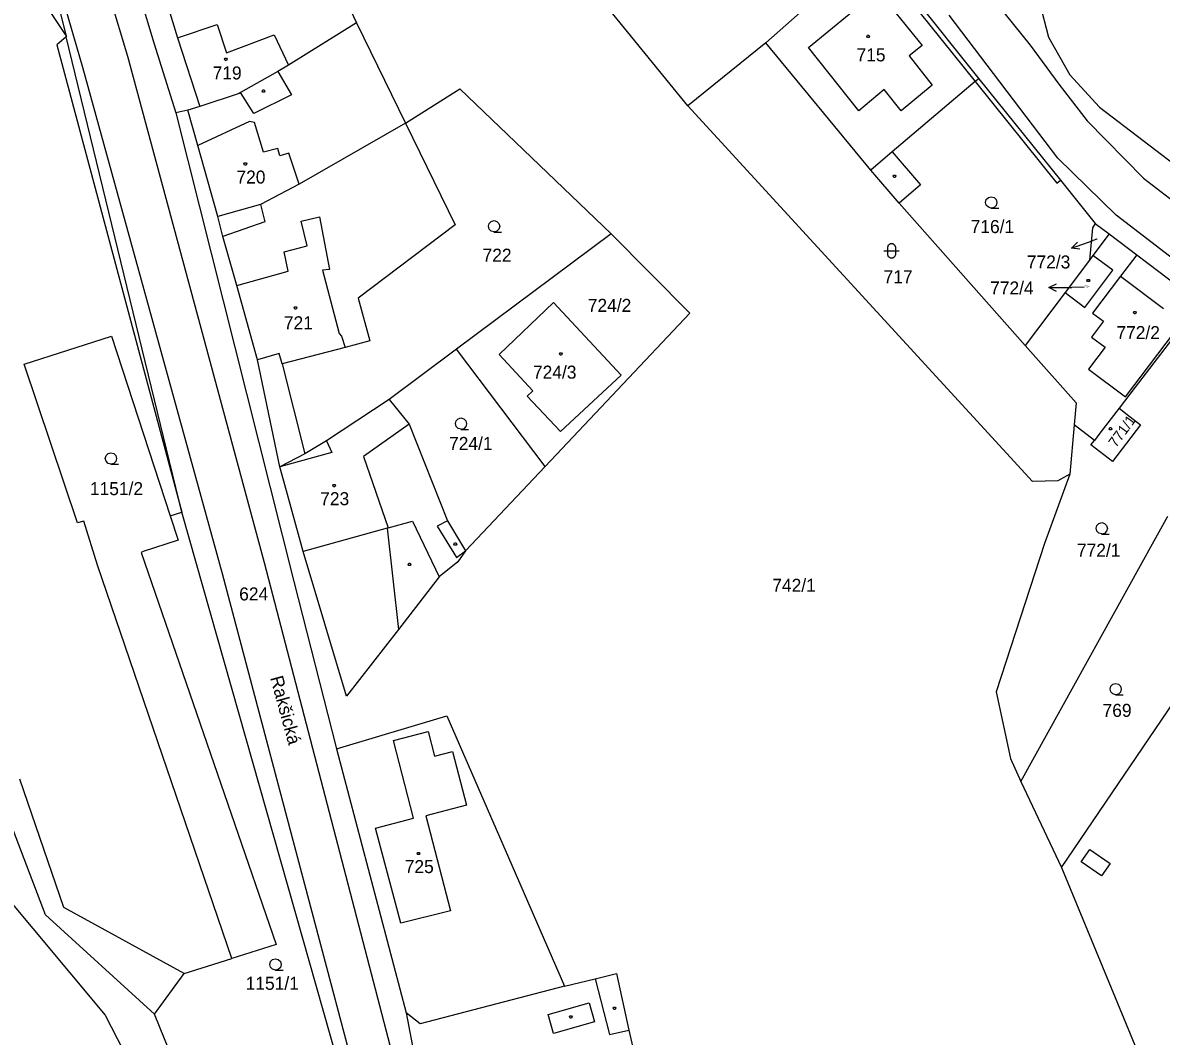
# Model space of a CAD drawing. Extents: x -621797 to -620972, y -1175539 to -1174697.
# Drawn here: x -621354.5 to -621205.7, y -1175263 to -1175130.5 of the extents above; entities that cross this region are included whole.
import ezdxf

# ---------------------------------------------------------------- set-up
doc = ezdxf.new("R2010")
doc.units = 0
for name, color, linetype in [('INZ mimo EON - nadz', 7, 'Continuous'), ('Rozvod plynu EON', 7, 'Continuous'), ('SDEL EON', 7, 'Continuous'), ('SDEL EON - popis', 7, 'Continuous'), ('Silnoproud EON', 7, 'Continuous'), ('Silnoproud EON - popis', 7, 'Continuous')]:
    doc.layers.add(name, color=color, linetype=linetype)

msp = doc.modelspace()

# ---------------------------------------------------------------- linework, layer by layer
at = {"layer": 'INZ mimo EON - nadz'}
for p, q in [((-621214.09, -1175158.81), (-621214.59, -1175158.99)), ((-621217.407, -1175160.022), (-621214.59, -1175158.99)), ((-621220.37, -1175165.164), (-621217.37, -1175165.13)), ((-621215.74, -1175165.11), (-621217.37, -1175165.13))]:
    msp.add_line(p, q, dxfattribs=at)
for points in [[(-621216.296, -1175160.148), (-621217.407, -1175160.022), (-621216.64, -1175159.209)], [(-621219.364, -1175165.652), (-621220.37, -1175165.164), (-621219.375, -1175164.652)]]:
    msp.add_lwpolyline(points, dxfattribs=at)
at = {"layer": 'Rozvod plynu EON'}
for points in [[(-621243.88, -1175132.18), (-621243.79, -1175132.33), (-621243.88, -1175132.48), (-621244.06, -1175132.48), (-621244.15, -1175132.33), (-621244.06, -1175132.18)], [(-621327.84, -1175135.17), (-621327.75, -1175135.32), (-621327.84, -1175135.47), (-621328.02, -1175135.47), (-621328.11, -1175135.32), (-621328.02, -1175135.17)], [(-621322.93, -1175139.33), (-621322.84, -1175139.48), (-621322.93, -1175139.63), (-621323.11, -1175139.63), (-621323.2, -1175139.48), (-621323.11, -1175139.33)], [(-621325.3, -1175148.84), (-621325.21, -1175148.99), (-621325.3, -1175149.14), (-621325.48, -1175149.14), (-621325.57, -1175148.99), (-621325.48, -1175148.84)], [(-621240.45, -1175150.45), (-621240.36, -1175150.6), (-621240.45, -1175150.75), (-621240.63, -1175150.75), (-621240.72, -1175150.6), (-621240.63, -1175150.45)], [(-621215.11, -1175164.08), (-621215.02, -1175164.23), (-621215.11, -1175164.38), (-621215.29, -1175164.38), (-621215.38, -1175164.23), (-621215.29, -1175164.08)], [(-621318.73, -1175167.67), (-621318.64, -1175167.82), (-621318.73, -1175167.97), (-621318.91, -1175167.97), (-621319, -1175167.82), (-621318.91, -1175167.67)], [(-621209.02, -1175168.28), (-621208.93, -1175168.43), (-621209.02, -1175168.58), (-621209.2, -1175168.58), (-621209.29, -1175168.43), (-621209.2, -1175168.28)], [(-621284.06, -1175173.67), (-621283.97, -1175173.82), (-621284.06, -1175173.97), (-621284.24, -1175173.97), (-621284.33, -1175173.82), (-621284.24, -1175173.67)], [(-621212.22, -1175183.45), (-621212.13, -1175183.6), (-621212.22, -1175183.75), (-621212.4, -1175183.75), (-621212.49, -1175183.6), (-621212.4, -1175183.45)], [(-621313.69, -1175190.88), (-621313.6, -1175191.03), (-621313.69, -1175191.18), (-621313.87, -1175191.18), (-621313.96, -1175191.03), (-621313.87, -1175190.88)], [(-621297.85, -1175198.53), (-621297.76, -1175198.68), (-621297.85, -1175198.83), (-621298.03, -1175198.83), (-621298.12, -1175198.68), (-621298.03, -1175198.53)], [(-621303.84, -1175201.19), (-621303.75, -1175201.34), (-621303.84, -1175201.49), (-621304.02, -1175201.49), (-621304.11, -1175201.34), (-621304.02, -1175201.19)], [(-621302.68, -1175238.98), (-621302.59, -1175239.13), (-621302.68, -1175239.28), (-621302.86, -1175239.28), (-621302.95, -1175239.13), (-621302.86, -1175238.98)], [(-621277.06, -1175259.21), (-621276.97, -1175259.36), (-621277.06, -1175259.51), (-621277.24, -1175259.51), (-621277.33, -1175259.36), (-621277.24, -1175259.21)], [(-621282.76, -1175260.34), (-621282.67, -1175260.49), (-621282.76, -1175260.64), (-621282.94, -1175260.64), (-621283.03, -1175260.49), (-621282.94, -1175260.34)]]:
    msp.add_lwpolyline(points, close=True, dxfattribs=at)
at = {"layer": 'SDEL EON'}
for points in [[(-621227.89, -1175154.76), (-621228.27, -1175154.66), (-621228.54, -1175154.39), (-621228.64, -1175154.02), (-621228.54, -1175153.65), (-621228.27, -1175153.38), (-621227.9, -1175153.28), (-621227.53, -1175153.38), (-621227.26, -1175153.65), (-621227.16, -1175154.03), (-621227.26, -1175154.41), (-621227.53, -1175154.68), (-621227.91, -1175154.78), (-621226.91, -1175154.78)], [(-621292.87, -1175157.88), (-621293.25, -1175157.78), (-621293.52, -1175157.51), (-621293.62, -1175157.14), (-621293.52, -1175156.77), (-621293.25, -1175156.5), (-621292.88, -1175156.4), (-621292.51, -1175156.5), (-621292.24, -1175156.77), (-621292.14, -1175157.15), (-621292.24, -1175157.53), (-621292.51, -1175157.8), (-621292.89, -1175157.9), (-621291.89, -1175157.9)], [(-621241.93, -1175160.36), (-621240.66, -1175160.36), (-621239.93, -1175160.36)], [(-621297.19, -1175183.68), (-621297.57, -1175183.58), (-621297.84, -1175183.31), (-621297.94, -1175182.94), (-621297.84, -1175182.57), (-621297.57, -1175182.3), (-621297.2, -1175182.2), (-621296.83, -1175182.3), (-621296.56, -1175182.57), (-621296.46, -1175182.95), (-621296.56, -1175183.33), (-621296.83, -1175183.6), (-621297.21, -1175183.7), (-621296.21, -1175183.7)], [(-621342.95, -1175188.23), (-621343.33, -1175188.13), (-621343.6, -1175187.86), (-621343.7, -1175187.49), (-621343.6, -1175187.12), (-621343.33, -1175186.85), (-621342.96, -1175186.75), (-621342.59, -1175186.85), (-621342.32, -1175187.12), (-621342.22, -1175187.5), (-621342.32, -1175187.88), (-621342.59, -1175188.15), (-621342.97, -1175188.25), (-621341.97, -1175188.25)], [(-621213.44, -1175197.36), (-621213.82, -1175197.26), (-621214.09, -1175196.99), (-621214.19, -1175196.62), (-621214.09, -1175196.25), (-621213.82, -1175195.98), (-621213.45, -1175195.88), (-621213.08, -1175195.98), (-621212.81, -1175196.25), (-621212.71, -1175196.63), (-621212.81, -1175197.01), (-621213.08, -1175197.28), (-621213.46, -1175197.38), (-621212.46, -1175197.38)], [(-621211.62, -1175218.38), (-621212, -1175218.28), (-621212.27, -1175218.01), (-621212.37, -1175217.64), (-621212.27, -1175217.27), (-621212, -1175217), (-621211.63, -1175216.9), (-621211.26, -1175217), (-621210.99, -1175217.27), (-621210.89, -1175217.65), (-621210.99, -1175218.03), (-621211.26, -1175218.3), (-621211.64, -1175218.4), (-621210.64, -1175218.4)], [(-621321.44, -1175254.36), (-621321.82, -1175254.26), (-621322.09, -1175253.99), (-621322.19, -1175253.62), (-621322.09, -1175253.25), (-621321.82, -1175252.98), (-621321.45, -1175252.88), (-621321.08, -1175252.98), (-621320.81, -1175253.25), (-621320.71, -1175253.63), (-621320.81, -1175254.01), (-621321.08, -1175254.28), (-621321.46, -1175254.38), (-621320.46, -1175254.38)]]:
    msp.add_lwpolyline(points, dxfattribs=at)
msp.add_lwpolyline([(-621241.43, -1175159.86), (-621241.33, -1175159.57), (-621241.08, -1175159.39), (-621240.77, -1175159.39), (-621240.52, -1175159.57), (-621240.42, -1175159.86), (-621240.42, -1175160.86), (-621240.52, -1175161.15), (-621240.77, -1175161.33), (-621241.08, -1175161.33), (-621241.33, -1175161.15), (-621241.43, -1175160.86)], close=True, dxfattribs=at)
at = {"layer": 'SDEL EON - popis'}
for p, q in [((-621347.7, -1175112.01), (-621340.8, -1175134.9)), ((-621346.63, -1175136.41), (-621353.17, -1175113.73)), ((-621243.2, -1175121.7), (-621229.98, -1175138.22)), ((-621251.77, -1175133.76), (-621242.73, -1175126.34)), ((-621242.73, -1175126.34), (-621236.94, -1175133.53)), ((-621335.58, -1175128.26), (-621334.24, -1175132.49)), ((-621227.17, -1175128.08), (-621222.79, -1175133.49)), ((-621219.21, -1175148.23), (-621233.41, -1175129.53)), ((-621334.24, -1175132.49), (-621329.09, -1175130.78)), ((-621329.09, -1175130.78), (-621327.84, -1175134.49)), ((-621327.84, -1175134.49), (-621321.63, -1175132.14)), ((-621321.63, -1175132.14), (-621319.76, -1175136.07)), ((-621348.82, -1175132.37), (-621350.04, -1175133.42)), ((-621350.04, -1175133.42), (-621333.69, -1175194.53)), ((-621334.24, -1175132.49), (-621331.32, -1175141.47)), ((-621236.94, -1175133.53), (-621238.64, -1175134.85)), ((-621222.79, -1175133.49), (-621219.07, -1175138.57)), ((-621340.8, -1175134.9), (-621322.93, -1175201.08)), ((-621245.19, -1175142.04), (-621251.77, -1175133.76)), ((-621238.64, -1175134.85), (-621235.62, -1175138.69)), ((-621328.38, -1175202.58), (-621346.63, -1175136.41)), ((-621321.12, -1175136.92), (-621319.35, -1175139.96)), ((-621241.88, -1175139.26), (-621245.19, -1175142.04)), ((-621239.65, -1175142.05), (-621241.88, -1175139.26)), ((-621235.62, -1175138.69), (-621239.65, -1175142.05)), ((-621229.98, -1175138.22), (-621219.33, -1175151.5)), ((-621219.07, -1175138.57), (-621215.37, -1175143.37)), ((-621324.26, -1175142.41), (-621326.02, -1175139.66)), ((-621319.35, -1175139.96), (-621324.26, -1175142.41)), ((-621324.84, -1175143.43), (-621331.59, -1175146.57)), ((-621324.21, -1175143.57), (-621324.84, -1175143.43)), ((-621323, -1175147.46), (-621324.21, -1175143.57)), ((-621215.37, -1175143.37), (-621208, -1175150.85)), ((-621321.16, -1175146.97), (-621323, -1175147.46)), ((-621320.88, -1175147.92), (-621321.16, -1175146.97)), ((-621319.72, -1175147.57), (-621320.88, -1175147.92)), ((-621318.35, -1175151.66), (-621319.72, -1175147.57)), ((-621240.85, -1175147.41), (-621243.63, -1175149.8)), ((-621211.57, -1175155.68), (-621219.21, -1175148.23)), ((-621219.33, -1175151.5), (-621218.86, -1175151.13)), ((-621208, -1175150.85), (-621101.85, -1175232.68)), ((-621323.42, -1175154.3), (-621322.86, -1175156.55)), ((-621318.07, -1175156.49), (-621315.69, -1175155.9)), ((-621315.69, -1175155.9), (-621314.39, -1175162.79)), ((-621089.77, -1175249.76), (-621211.57, -1175155.68)), ((-621322.86, -1175156.55), (-621328.31, -1175158.48)), ((-621317.31, -1175159.68), (-621318.07, -1175156.49)), ((-621320.3, -1175160.47), (-621317.31, -1175159.68)), ((-621319.77, -1175163.01), (-621320.3, -1175160.47)), ((-621208.88, -1175160.86), (-621211.01, -1175163.66)), ((-621326.52, -1175164.88), (-621319.77, -1175163.01)), ((-621314.39, -1175162.79), (-621315.29, -1175162.86)), ((-621315.29, -1175162.86), (-621313.12, -1175171.18)), ((-621211.01, -1175163.66), (-621214.66, -1175168.49)), ((-621211.01, -1175163.66), (-621205.39, -1175167.9)), ((-621214.66, -1175168.49), (-621213.23, -1175169.56)), ((-621213.23, -1175169.56), (-621214.78, -1175171.62)), ((-621210.34, -1175179.44), (-621202.99, -1175169.71)), ((-621313.12, -1175171.18), (-621312.81, -1175171.5)), ((-621312.81, -1175171.5), (-621312.34, -1175172.98)), ((-621214.78, -1175171.62), (-621213.01, -1175172.95)), ((-621320.96, -1175173.78), (-621323.8, -1175174.58)), ((-621320.59, -1175175.12), (-621320.96, -1175173.78)), ((-621213.01, -1175172.95), (-621215.16, -1175175.8)), ((-621215.16, -1175175.8), (-621210.34, -1175179.44)), ((-621303.99, -1175183.02), (-621309.96, -1175187.22)), ((-621314.8, -1175185.2), (-621314.09, -1175186.71)), ((-621314.09, -1175186.71), (-621320.86, -1175188.59)), ((-621309.96, -1175187.22), (-621306.71, -1175196.57)), ((-621306.71, -1175196.57), (-621303.56, -1175195.7)), ((-621303.56, -1175195.7), (-621300.05, -1175202.96)), ((-621298.95, -1175195.66), (-621300.33, -1175196.33)), ((-621306.86, -1175196.61), (-621317.83, -1175199.64)), ((-621306.71, -1175196.57), (-621306.86, -1175196.61)), ((-621306.86, -1175196.61), (-621305.39, -1175209.83)), ((-621300.33, -1175196.33), (-621297.79, -1175200.42)), ((-621297.79, -1175200.42), (-621296.62, -1175199.56)), ((-621322.93, -1175201.08), (-621305.9, -1175266.54)), ((-621311.1, -1175267.73), (-621328.38, -1175202.58)), ((-621306.01, -1175224.38), (-621301.51, -1175223.19)), ((-621303.41, -1175234.5), (-621306.01, -1175224.38)), ((-621301.51, -1175223.19), (-621300.68, -1175226.39)), ((-621300.68, -1175226.39), (-621298.33, -1175225.8)), ((-621298.33, -1175225.8), (-621296.5, -1175232.81)), ((-621368.01, -1175231.22), (-621343.71, -1175260.26)), ((-621296.5, -1175232.81), (-621301.8, -1175234.19)), ((-621308.36, -1175235.81), (-621303.41, -1175234.5)), ((-621301.8, -1175234.19), (-621298.56, -1175246.64)), ((-621305.05, -1175248.25), (-621308.36, -1175235.81)), ((-621216.12, -1175240.21), (-621214.99, -1175238.59)), ((-621214.99, -1175238.59), (-621212.34, -1175240.43)), ((-621213.47, -1175242.06), (-621216.12, -1175240.21)), ((-621212.34, -1175240.43), (-621213.47, -1175242.06)), ((-621298.56, -1175246.64), (-621305.05, -1175248.25)), ((-621279.66, -1175255.51), (-621277.81, -1175262.77)), ((-621285.81, -1175260.19), (-621280.43, -1175258.66)), ((-621280.43, -1175258.66), (-621279.74, -1175261.12)), ((-621343.71, -1175260.26), (-621329.23, -1175288.45)), ((-621285.11, -1175262.64), (-621285.81, -1175260.19)), ((-621279.74, -1175261.12), (-621285.11, -1175262.64)), ((-621277.81, -1175262.77), (-621275.27, -1175262.22))]:
    msp.add_line(p, q, dxfattribs=at)
at = {"layer": 'Silnoproud EON'}
for p, q in [((-621267.53, -1175141.41), (-621313.11, -1175085.57)), ((-621317.61, -1175116.28), (-621310.86, -1175130.56)), ((-621243.11, -1175120.86), (-621229.53, -1175137.85)), ((-621245.89, -1175123.03), (-621257.36, -1175133.16)), ((-621348.77, -1175132.34), (-621350.54, -1175125.06)), ((-621339.39, -1175126.33), (-621337.37, -1175133.15)), ((-621351.04, -1175128.93), (-621348.77, -1175132.34)), ((-621221.57, -1175127.89), (-621220.4, -1175132.44)), ((-621310.86, -1175130.56), (-621319.76, -1175136.07)), ((-621310.86, -1175130.56), (-621304.45, -1175143.66)), ((-621348.82, -1175132.37), (-621348.77, -1175132.34)), ((-621333.69, -1175194.53), (-621348.82, -1175132.37)), ((-621337.37, -1175133.15), (-621334.46, -1175142.32)), ((-621257.36, -1175133.16), (-621267.53, -1175141.41)), ((-621243.63, -1175149.8), (-621257.36, -1175133.16)), ((-621220.4, -1175132.44), (-621217.62, -1175137.35)), ((-621319.76, -1175136.07), (-621321.12, -1175136.92)), ((-621321.12, -1175136.92), (-621326.02, -1175139.66)), ((-621229.53, -1175137.85), (-621229.98, -1175138.22)), ((-621229.53, -1175137.85), (-621218.86, -1175151.13)), ((-621217.62, -1175137.35), (-621213.76, -1175141.57)), ((-621304.45, -1175143.66), (-621297.36, -1175139.17)), ((-621297.36, -1175139.17), (-621277.58, -1175158.14)), ((-621229.98, -1175138.22), (-621240.85, -1175147.41)), ((-621326.19, -1175139.77), (-621331.32, -1175141.47)), ((-621326.02, -1175139.66), (-621326.19, -1175139.77)), ((-621332.91, -1175141.97), (-621334.46, -1175142.32)), ((-621334.46, -1175142.32), (-621319.05, -1175203.58)), ((-621331.32, -1175141.47), (-621332.91, -1175141.97)), ((-621331.59, -1175146.57), (-621332.91, -1175141.97)), ((-621222.48, -1175190.51), (-621267.53, -1175141.41)), ((-621213.76, -1175141.57), (-621176.1, -1175170.37)), ((-621304.45, -1175143.66), (-621318.35, -1175151.66)), ((-621304.45, -1175143.66), (-621297.95, -1175156.95)), ((-621329, -1175155.85), (-621331.59, -1175146.57)), ((-621240.85, -1175147.41), (-621237.13, -1175151.73)), ((-621239.91, -1175154.12), (-621243.63, -1175149.8)), ((-621218.86, -1175151.13), (-621214.29, -1175156.77)), ((-621318.35, -1175151.66), (-621323.42, -1175154.3)), ((-621237.13, -1175151.73), (-621239.91, -1175154.12)), ((-621323.42, -1175154.3), (-621329, -1175155.85)), ((-621223.44, -1175172.71), (-621239.91, -1175154.12)), ((-621328.31, -1175158.48), (-621329, -1175155.85)), ((-621297.95, -1175156.95), (-621310.65, -1175166.54)), ((-621214.67, -1175157.33), (-621215.06, -1175161.57)), ((-621214.29, -1175156.77), (-621214.67, -1175157.33)), ((-621214.29, -1175156.77), (-621212.47, -1175158.15)), ((-621326.52, -1175164.88), (-621328.31, -1175158.48)), ((-621277.58, -1175158.14), (-621297.79, -1175173.22)), ((-621277.58, -1175158.14), (-621267.28, -1175168.52)), ((-621212.47, -1175158.15), (-621214.6, -1175160.96)), ((-621212.47, -1175158.15), (-621208.88, -1175160.86)), ((-621215.06, -1175161.57), (-621218.24, -1175165.79)), ((-621214.6, -1175160.96), (-621215.06, -1175161.57)), ((-621212.02, -1175162.89), (-621214.6, -1175160.96)), ((-621208.88, -1175160.86), (-621203.27, -1175165.11)), ((-621215.68, -1175167.74), (-621212.02, -1175162.89)), ((-621323.8, -1175174.58), (-621326.52, -1175164.88)), ((-621218.24, -1175165.79), (-621223.44, -1175172.71)), ((-621218.24, -1175165.79), (-621215.68, -1175167.74)), ((-621310.65, -1175166.54), (-621309.1, -1175172.13)), ((-621292.23, -1175173.89), (-621285.13, -1175167.12)), ((-621285.13, -1175167.12), (-621276.28, -1175176.62)), ((-621200.63, -1175167.11), (-621209.09, -1175178.17)), ((-621267.28, -1175168.52), (-621286.2, -1175188.53)), ((-621354.3, -1175175.16), (-621342.9, -1175171.49)), ((-621342.9, -1175171.49), (-621335.22, -1175194.98)), ((-621309.1, -1175172.13), (-621312.34, -1175172.98)), ((-621312.34, -1175172.98), (-621320.59, -1175175.12)), ((-621297.79, -1175173.22), (-621306.59, -1175179.79)), ((-621286.2, -1175188.53), (-621297.79, -1175173.22)), ((-621216.8, -1175180.21), (-621223.44, -1175172.71)), ((-621347.32, -1175195.92), (-621354.3, -1175175.16)), ((-621320.86, -1175188.59), (-621323.8, -1175174.58)), ((-621320.59, -1175175.12), (-621317.62, -1175186.87)), ((-621287.79, -1175178.65), (-621292.23, -1175173.89)), ((-621276.28, -1175176.62), (-621284.18, -1175183.99)), ((-621209.09, -1175178.17), (-621211.19, -1175180.92)), ((-621306.59, -1175179.79), (-621314.8, -1175185.2)), ((-621306.59, -1175179.79), (-621303.99, -1175183.02)), ((-621288.53, -1175179.34), (-621287.79, -1175178.65)), ((-621284.18, -1175183.99), (-621288.53, -1175179.34)), ((-621216.8, -1175180.21), (-621217.06, -1175183.1)), ((-621211.19, -1175180.92), (-621213.68, -1175184.17)), ((-621211.19, -1175180.92), (-621210.14, -1175181.73)), ((-621210.14, -1175181.73), (-621208.37, -1175183.08)), ((-621303.99, -1175183.02), (-621298.95, -1175195.66)), ((-621217.06, -1175183.1), (-621217.63, -1175189.53)), ((-621214.41, -1175185.13), (-621217.06, -1175183.1)), ((-621213.68, -1175184.17), (-621214.41, -1175185.13)), ((-621208.37, -1175183.08), (-621212.05, -1175187.88)), ((-621314.8, -1175185.2), (-621317.62, -1175186.87)), ((-621214.86, -1175185.72), (-621214.41, -1175185.13)), ((-621212.05, -1175187.88), (-621214.86, -1175185.72)), ((-621317.62, -1175186.87), (-621320.86, -1175188.59)), ((-621320.34, -1175190.48), (-621320.86, -1175188.59)), ((-621286.2, -1175188.53), (-621296.62, -1175199.56)), ((-621217.63, -1175189.53), (-621220.95, -1175198.63)), ((-621217.63, -1175189.53), (-621219.21, -1175190.4)), ((-621317.83, -1175199.64), (-621320.34, -1175190.48)), ((-621219.21, -1175190.4), (-621222.48, -1175190.51)), ((-621335.22, -1175194.98), (-621333.69, -1175194.53)), ((-621312.81, -1175268.13), (-621333.69, -1175194.53)), ((-621346.5, -1175195.69), (-621347.32, -1175195.92)), ((-621344.72, -1175201.46), (-621346.5, -1175195.69)), ((-621335.22, -1175194.98), (-621334.18, -1175198.17)), ((-621298.95, -1175195.66), (-621296.62, -1175199.56)), ((-621224.04, -1175229.72), (-621204.82, -1175195.05)), ((-621334.18, -1175198.17), (-621338.73, -1175199.67)), ((-621220.95, -1175198.63), (-621227.25, -1175217.98)), ((-621338.73, -1175199.67), (-621339.02, -1175199.77)), ((-621339.02, -1175199.77), (-621321.35, -1175251.01)), ((-621312.17, -1175218.55), (-621317.83, -1175199.64)), ((-621296.62, -1175199.56), (-621297.63, -1175201.01)), ((-621327.16, -1175252.85), (-621344.72, -1175201.46)), ((-621297.63, -1175201.01), (-621300.05, -1175202.96)), ((-621319.05, -1175203.58), (-621313.49, -1175225.44)), ((-621300.05, -1175202.96), (-621305.39, -1175209.83)), ((-621218.73, -1175240.96), (-621195.95, -1175207.41)), ((-621305.39, -1175209.83), (-621312.17, -1175218.55)), ((-621227.25, -1175217.98), (-621225.36, -1175226.72)), ((-621313.49, -1175225.44), (-621299.03, -1175221.15)), ((-621299.03, -1175221.15), (-621283.68, -1175256.48)), ((-621313.49, -1175225.44), (-621304.37, -1175259.95)), ((-621225.36, -1175226.72), (-621224.04, -1175229.72)), ((-621349.1, -1175246.19), (-621354.87, -1175229.42)), ((-621224.04, -1175229.72), (-621218.73, -1175240.96)), ((-621351.49, -1175247.14), (-621357.81, -1175230.66)), ((-621218.73, -1175240.96), (-621208.28, -1175266.18)), ((-621333.4, -1175254.83), (-621349.1, -1175246.19)), ((-621337.28, -1175260.13), (-621351.49, -1175247.14)), ((-621321.35, -1175251.01), (-621327.16, -1175252.85)), ((-621333.4, -1175254.83), (-621327.16, -1175252.85)), ((-621337.28, -1175260.13), (-621333.4, -1175254.83)), ((-621283.68, -1175256.48), (-621279.66, -1175255.51)), ((-621279.66, -1175255.51), (-621276.89, -1175254.81)), ((-621276.89, -1175254.81), (-621275.27, -1175262.22)), ((-621283.68, -1175256.48), (-621302.53, -1175261.39)), ((-621331.21, -1175274.92), (-621337.28, -1175260.13)), ((-621304.37, -1175259.95), (-621303.22, -1175265.93)), ((-621302.53, -1175261.39), (-621304.37, -1175259.95)), ((-621275.27, -1175262.22), (-621273.28, -1175270.82))]:
    msp.add_line(p, q, dxfattribs=at)

# ---------------------------------------------------------------- texts
at = {"layer": 'INZ mimo EON - nadz'}
for s, p in [('772/3', (-621223.244, -1175162.66)), ('772/4', (-621228.036, -1175166.06)), ('742/1', (-621256.513, -1175204.92))]:
    msp.add_text(s, height=1.7, dxfattribs=at).set_placement(p)
msp.add_text('Rakšická', height=1.7, rotation=285.27569, dxfattribs=at).set_placement((-621322.156, -1175216.154))
at = {"layer": 'Silnoproud EON - popis'}
for s, height, p in [('715', 1.7, (-621245.503, -1175135.59)), ('719', 1.7, (-621329.663, -1175137.95)), ('720', 1.7, (-621326.553, -1175151.56)), ('716/1', 1.7, (-621230.587, -1175158.03)), ('772/3', 0.1, (-621214.297, -1175158.81)), ('722', 1.7, (-621294.383, -1175161.77)), ('717', 1.7, (-621241.963, -1175164.6)), ('772/4', 0.2, (-621215.712, -1175165.11)), ('724/2', 1.7, (-621280.63, -1175168.33)), ('721', 1.7, (-621320.353, -1175170.61)), ('772/2', 1.7, (-621211.533, -1175171.89)), ('724/3', 1.7, (-621287.794, -1175177.06)), ('724/1', 1.7, (-621298.763, -1175186.38)), ('1151/2', 1.7, (-621345.707, -1175192.29)), ('723', 1.7, (-621315.603, -1175193.6)), ('772/1', 1.7, (-621216.693, -1175200.34)), ('624', 1.7, (-621326.193, -1175206.05)), ('769', 1.7, (-621213.343, -1175221.27)), ('725', 1.7, (-621304.553, -1175241.69)), ('1151/1', 1.7, (-621325.347, -1175256.95))]:
    msp.add_text(s, height=height, dxfattribs=at).set_placement(p)
msp.add_text('771/1', height=1.36, rotation=53.85803, dxfattribs=at).set_placement((-621211.588, -1175186.157))

doc.saveas('drawing.dxf')
